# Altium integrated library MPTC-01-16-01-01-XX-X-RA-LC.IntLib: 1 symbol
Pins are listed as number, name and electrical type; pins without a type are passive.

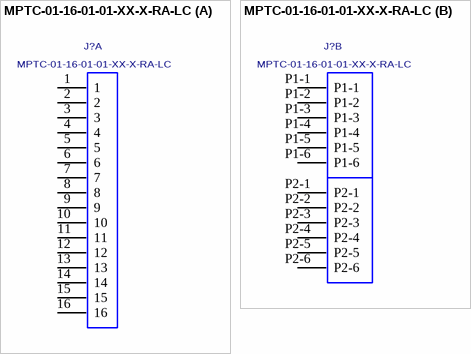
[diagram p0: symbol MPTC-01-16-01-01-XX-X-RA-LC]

## MPTC-01-16-01-01-XX-X-RA-LC
designator J?
RIGHT ANGLE POWER TERMINAL; MANUFACTURER: SAMTEC
footprint MPTC-01-16-01-01-XX-X-RA-LC
part A pins: 1, 2, 3, 4, 5, 6, 7, 8, 9, 10, 11, 12, 13, 14, 15, 16
part B pins: P1-1, P1-2, P1-3, P1-4, P1-5, P1-6, P2-1, P2-2, P2-3, P2-4, P2-5, P2-6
